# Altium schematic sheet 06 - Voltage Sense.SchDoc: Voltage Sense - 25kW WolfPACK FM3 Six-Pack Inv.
size 431 x 279 mm; Date: 01/2024; DocumentNumber: CRD25DA12N-FMC; Revision: 1.2; SheetNumber: 6; SheetTotal: 8; SheetSize: B
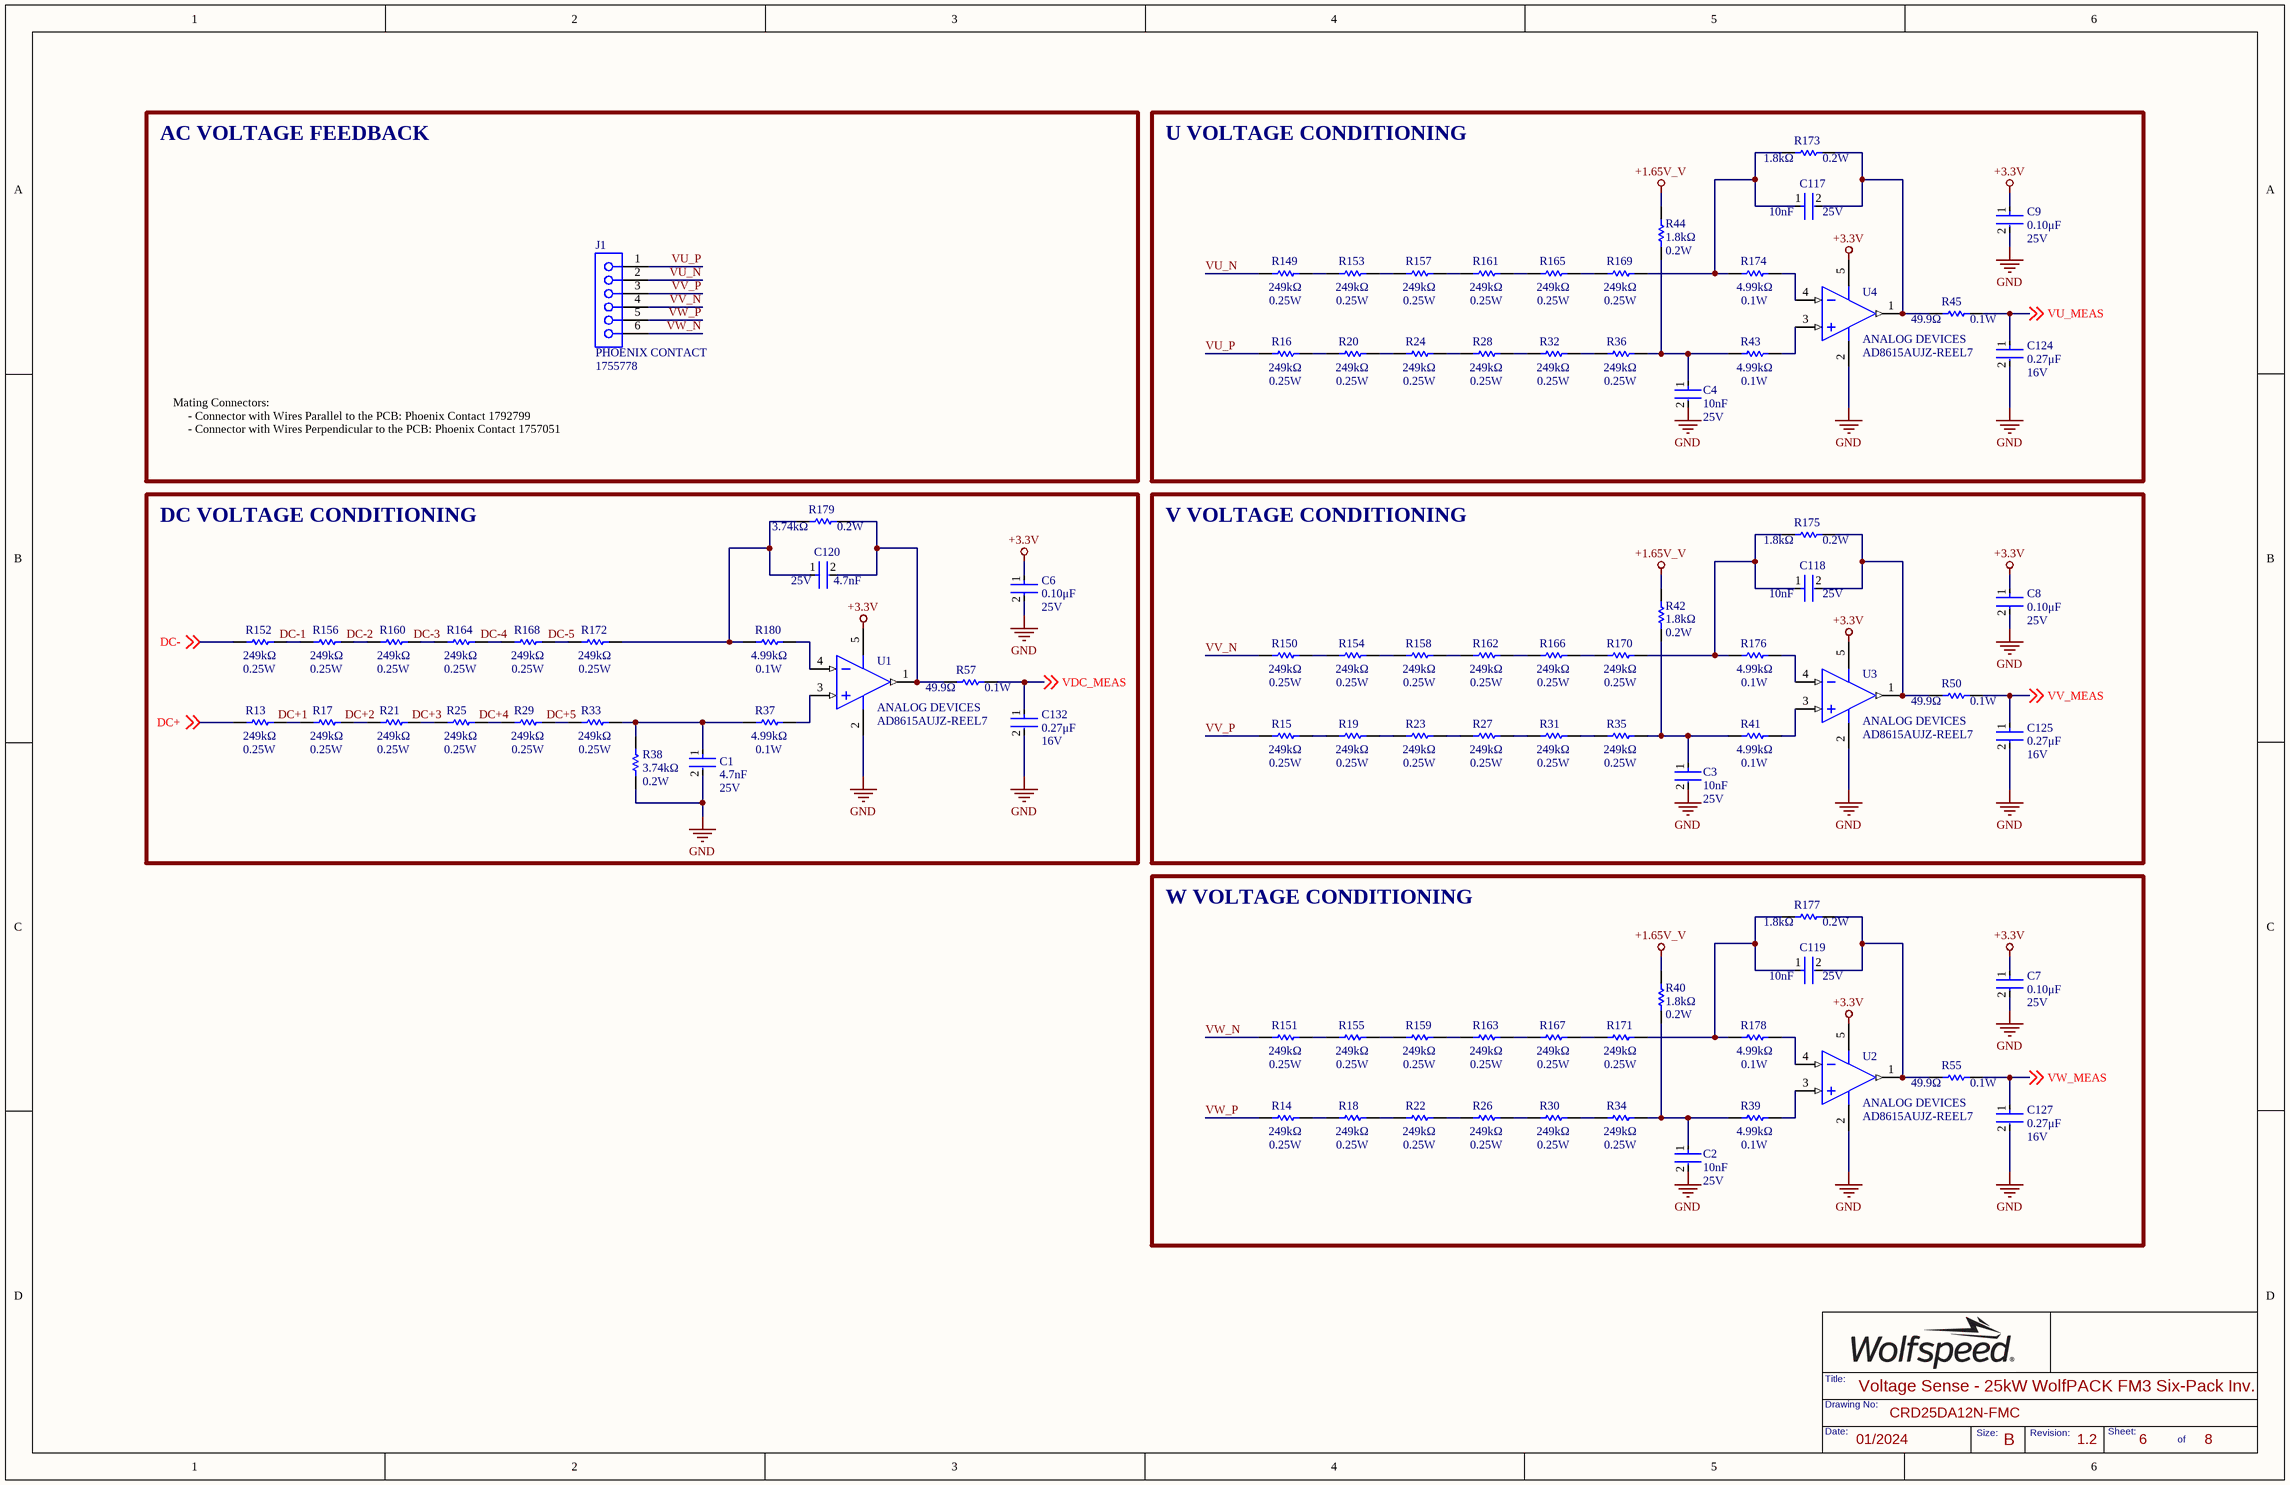
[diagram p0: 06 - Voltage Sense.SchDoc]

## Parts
C1  Voltage Rating: 25V  Capacitance: 4.7nF  [FP-C0603C-CF-IPC_B]  (hidden comment: C0603C472K3RAC7867)
C2  value 10nF  Voltage Rating: 25V  [FP-C0603C-CF-IPC_B]  (hidden comment: CL10B103KA8WPNC)
C3  value 10nF  Voltage Rating: 25V  [FP-C0603C-CF-IPC_B]  (hidden comment: CL10B103KA8WPNC)
C4  value 10nF  Voltage Rating: 25V  [FP-C0603C-CF-IPC_B]  (hidden comment: CL10B103KA8WPNC)
C6  Voltage Rating: 25V  Capacitance: 0.10μF  [FP-C0603C-CF-IPC_B]  (hidden comment: C0603C104K3RACTU)
C7  Voltage Rating: 25V  Capacitance: 0.10μF  [FP-C0603C-CF-IPC_B]  (hidden comment: C0603C104K3RACTU)
C8  Voltage Rating: 25V  Capacitance: 0.10μF  [FP-C0603C-CF-IPC_B]  (hidden comment: C0603C104K3RACTU)
C9  Voltage Rating: 25V  Capacitance: 0.10μF  [FP-C0603C-CF-IPC_B]  (hidden comment: C0603C104K3RACTU)
C117  value 10nF  Voltage Rating: 25V  [FP-C0603C-CF-IPC_B]  (hidden comment: CL10B103KA8WPNC)
C118  value 10nF  Voltage Rating: 25V  [FP-C0603C-CF-IPC_B]  (hidden comment: CL10B103KA8WPNC)
C119  value 10nF  Voltage Rating: 25V  [FP-C0603C-CF-IPC_B]  (hidden comment: CL10B103KA8WPNC)
C120  Voltage Rating: 25V  Capacitance: 4.7nF  [FP-C0603C-CF-IPC_B]  (hidden comment: C0603C472K3RAC7867)
C124  Voltage Rating (DC): 16V  Capacitance: 0.27μF  [FP-GCM188-0_1-IPC_A]  (hidden comment: GCM188R71C274KA37D)
C125  Voltage Rating (DC): 16V  Capacitance: 0.27μF  [FP-GCM188-0_1-IPC_A]  (hidden comment: GCM188R71C274KA37D)
C127  Voltage Rating (DC): 16V  Capacitance: 0.27μF  [FP-GCM188-0_1-IPC_A]  (hidden comment: GCM188R71C274KA37D)
C132  Voltage Rating (DC): 16V  Capacitance: 0.27μF  [FP-GCM188-0_1-IPC_A]  (hidden comment: GCM188R71C274KA37D)
J1  1755778  Manufacturer Print: PHOENIX CONTACT  [1755778]
R13  Resistance: 249kΩ  Power: 0.25W  [RESC3216X65X50NL15T25]  (hidden comment: TNPW1206249KBEEA)
R14  Resistance: 249kΩ  Power: 0.25W  [RESC3216X65X50NL15T25]  (hidden comment: TNPW1206249KBEEA)
R15  Resistance: 249kΩ  Power: 0.25W  [RESC3216X65X50NL15T25]  (hidden comment: TNPW1206249KBEEA)
R16  Resistance: 249kΩ  Power: 0.25W  [RESC3216X65X50NL15T25]  (hidden comment: TNPW1206249KBEEA)
R17  Resistance: 249kΩ  Power: 0.25W  [RESC3216X65X50NL15T25]  (hidden comment: TNPW1206249KBEEA)
R18  Resistance: 249kΩ  Power: 0.25W  [RESC3216X65X50NL15T25]  (hidden comment: TNPW1206249KBEEA)
R19  Resistance: 249kΩ  Power: 0.25W  [RESC3216X65X50NL15T25]  (hidden comment: TNPW1206249KBEEA)
R20  Resistance: 249kΩ  Power: 0.25W  [RESC3216X65X50NL15T25]  (hidden comment: TNPW1206249KBEEA)
R21  Resistance: 249kΩ  Power: 0.25W  [RESC3216X65X50NL15T25]  (hidden comment: TNPW1206249KBEEA)
R22  Resistance: 249kΩ  Power: 0.25W  [RESC3216X65X50NL15T25]  (hidden comment: TNPW1206249KBEEA)
R23  Resistance: 249kΩ  Power: 0.25W  [RESC3216X65X50NL15T25]  (hidden comment: TNPW1206249KBEEA)
R24  Resistance: 249kΩ  Power: 0.25W  [RESC3216X65X50NL15T25]  (hidden comment: TNPW1206249KBEEA)
R25  Resistance: 249kΩ  Power: 0.25W  [RESC3216X65X50NL15T25]  (hidden comment: TNPW1206249KBEEA)
R26  Resistance: 249kΩ  Power: 0.25W  [RESC3216X65X50NL15T25]  (hidden comment: TNPW1206249KBEEA)
R27  Resistance: 249kΩ  Power: 0.25W  [RESC3216X65X50NL15T25]  (hidden comment: TNPW1206249KBEEA)
R28  Resistance: 249kΩ  Power: 0.25W  [RESC3216X65X50NL15T25]  (hidden comment: TNPW1206249KBEEA)
R29  Resistance: 249kΩ  Power: 0.25W  [RESC3216X65X50NL15T25]  (hidden comment: TNPW1206249KBEEA)
R30  Resistance: 249kΩ  Power: 0.25W  [RESC3216X65X50NL15T25]  (hidden comment: TNPW1206249KBEEA)
R31  Resistance: 249kΩ  Power: 0.25W  [RESC3216X65X50NL15T25]  (hidden comment: TNPW1206249KBEEA)
R32  Resistance: 249kΩ  Power: 0.25W  [RESC3216X65X50NL15T25]  (hidden comment: TNPW1206249KBEEA)
R33  Resistance: 249kΩ  Power: 0.25W  [RESC3216X65X50NL15T25]  (hidden comment: TNPW1206249KBEEA)
R34  Resistance: 249kΩ  Power: 0.25W  [RESC3216X65X50NL15T25]  (hidden comment: TNPW1206249KBEEA)
R35  Resistance: 249kΩ  Power: 0.25W  [RESC3216X65X50NL15T25]  (hidden comment: TNPW1206249KBEEA)
R36  Resistance: 249kΩ  Power: 0.25W  [RESC3216X65X50NL15T25]  (hidden comment: TNPW1206249KBEEA)
R37  Power Rating: 0.1W  Resistance: 4.99kΩ  [FP-MCR03-IPC_B]  (hidden comment: RC0603FR-074K99L)
R38  Max Power Dissipation: 0.2W  Resistance: 3.74kΩ  [FP-MCR03-IPC_B]  (hidden comment: ERJ-PB3B3741V)
R39  Power Rating: 0.1W  Resistance: 4.99kΩ  [FP-MCR03-IPC_B]  (hidden comment: RC0603FR-074K99L)
R40  Resistance: 1.8kΩ  Max Power Dissipation: 0.2W  [FP-MCR03-IPC_B]  (hidden comment: ERJ-PB3B1801V)
R41  Power Rating: 0.1W  Resistance: 4.99kΩ  [FP-MCR03-IPC_B]  (hidden comment: RC0603FR-074K99L)
R42  Resistance: 1.8kΩ  Max Power Dissipation: 0.2W  [FP-MCR03-IPC_B]  (hidden comment: ERJ-PB3B1801V)
R43  Power Rating: 0.1W  Resistance: 4.99kΩ  [FP-MCR03-IPC_B]  (hidden comment: RC0603FR-074K99L)
R44  Resistance: 1.8kΩ  Max Power Dissipation: 0.2W  [FP-MCR03-IPC_B]  (hidden comment: ERJ-PB3B1801V)
R45  Resistance: 49.9Ω  Power Rating: 0.1W  [FP-MCR03-IPC_B]  (hidden comment: ERJ-3EKF49R9V)
R50  Resistance: 49.9Ω  Power Rating: 0.1W  [FP-MCR03-IPC_B]  (hidden comment: ERJ-3EKF49R9V)
R55  Resistance: 49.9Ω  Power Rating: 0.1W  [FP-MCR03-IPC_B]  (hidden comment: ERJ-3EKF49R9V)
R57  Resistance: 49.9Ω  Power Rating: 0.1W  [FP-MCR03-IPC_B]  (hidden comment: ERJ-3EKF49R9V)
R149  Resistance: 249kΩ  Power: 0.25W  [RESC3216X65X50NL15T25]  (hidden comment: TNPW1206249KBEEA)
R150  Resistance: 249kΩ  Power: 0.25W  [RESC3216X65X50NL15T25]  (hidden comment: TNPW1206249KBEEA)
R151  Resistance: 249kΩ  Power: 0.25W  [RESC3216X65X50NL15T25]  (hidden comment: TNPW1206249KBEEA)
R152  Resistance: 249kΩ  Power: 0.25W  [RESC3216X65X50NL15T25]  (hidden comment: TNPW1206249KBEEA)
R153  Resistance: 249kΩ  Power: 0.25W  [RESC3216X65X50NL15T25]  (hidden comment: TNPW1206249KBEEA)
R154  Resistance: 249kΩ  Power: 0.25W  [RESC3216X65X50NL15T25]  (hidden comment: TNPW1206249KBEEA)
R155  Resistance: 249kΩ  Power: 0.25W  [RESC3216X65X50NL15T25]  (hidden comment: TNPW1206249KBEEA)
R156  Resistance: 249kΩ  Power: 0.25W  [RESC3216X65X50NL15T25]  (hidden comment: TNPW1206249KBEEA)
R157  Resistance: 249kΩ  Power: 0.25W  [RESC3216X65X50NL15T25]  (hidden comment: TNPW1206249KBEEA)
R158  Resistance: 249kΩ  Power: 0.25W  [RESC3216X65X50NL15T25]  (hidden comment: TNPW1206249KBEEA)
R159  Resistance: 249kΩ  Power: 0.25W  [RESC3216X65X50NL15T25]  (hidden comment: TNPW1206249KBEEA)
R160  Resistance: 249kΩ  Power: 0.25W  [RESC3216X65X50NL15T25]  (hidden comment: TNPW1206249KBEEA)
R161  Resistance: 249kΩ  Power: 0.25W  [RESC3216X65X50NL15T25]  (hidden comment: TNPW1206249KBEEA)
R162  Resistance: 249kΩ  Power: 0.25W  [RESC3216X65X50NL15T25]  (hidden comment: TNPW1206249KBEEA)
R163  Resistance: 249kΩ  Power: 0.25W  [RESC3216X65X50NL15T25]  (hidden comment: TNPW1206249KBEEA)
R164  Resistance: 249kΩ  Power: 0.25W  [RESC3216X65X50NL15T25]  (hidden comment: TNPW1206249KBEEA)
R165  Resistance: 249kΩ  Power: 0.25W  [RESC3216X65X50NL15T25]  (hidden comment: TNPW1206249KBEEA)
R166  Resistance: 249kΩ  Power: 0.25W  [RESC3216X65X50NL15T25]  (hidden comment: TNPW1206249KBEEA)
R167  Resistance: 249kΩ  Power: 0.25W  [RESC3216X65X50NL15T25]  (hidden comment: TNPW1206249KBEEA)
R168  Resistance: 249kΩ  Power: 0.25W  [RESC3216X65X50NL15T25]  (hidden comment: TNPW1206249KBEEA)
R169  Resistance: 249kΩ  Power: 0.25W  [RESC3216X65X50NL15T25]  (hidden comment: TNPW1206249KBEEA)
R170  Resistance: 249kΩ  Power: 0.25W  [RESC3216X65X50NL15T25]  (hidden comment: TNPW1206249KBEEA)
R171  Resistance: 249kΩ  Power: 0.25W  [RESC3216X65X50NL15T25]  (hidden comment: TNPW1206249KBEEA)
R172  Resistance: 249kΩ  Power: 0.25W  [RESC3216X65X50NL15T25]  (hidden comment: TNPW1206249KBEEA)
R173  Resistance: 1.8kΩ  Max Power Dissipation: 0.2W  [FP-MCR03-IPC_B]  (hidden comment: ERJ-PB3B1801V)
R174  Power Rating: 0.1W  Resistance: 4.99kΩ  [FP-MCR03-IPC_B]  (hidden comment: RC0603FR-074K99L)
R175  Resistance: 1.8kΩ  Max Power Dissipation: 0.2W  [FP-MCR03-IPC_B]  (hidden comment: ERJ-PB3B1801V)
R176  Power Rating: 0.1W  Resistance: 4.99kΩ  [FP-MCR03-IPC_B]  (hidden comment: RC0603FR-074K99L)
R177  Resistance: 1.8kΩ  Max Power Dissipation: 0.2W  [FP-MCR03-IPC_B]  (hidden comment: ERJ-PB3B1801V)
R178  Power Rating: 0.1W  Resistance: 4.99kΩ  [FP-MCR03-IPC_B]  (hidden comment: RC0603FR-074K99L)
R179  Max Power Dissipation: 0.2W  Resistance: 3.74kΩ  [FP-MCR03-IPC_B]  (hidden comment: ERJ-PB3B3741V)
R180  Power Rating: 0.1W  Resistance: 4.99kΩ  [FP-MCR03-IPC_B]  (hidden comment: RC0603FR-074K99L)
U1  Manufacturer: ANALOG DEVICES  [ADI-UJ-5_M]  (hidden comment: AD8615AUJZ-REEL7)
U2  Manufacturer: ANALOG DEVICES  [ADI-UJ-5_M]  (hidden comment: AD8615AUJZ-REEL7)
U3  Manufacturer: ANALOG DEVICES  [ADI-UJ-5_M]  (hidden comment: AD8615AUJZ-REEL7)
U4  Manufacturer: ANALOG DEVICES  [ADI-UJ-5_M]  (hidden comment: AD8615AUJZ-REEL7)

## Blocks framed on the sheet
AC VOLTAGE FEEDBACK: J1
U VOLTAGE CONDITIONING: C4 C9 C117 C124 R16 R20 R24 R28 R32 R36 R43-R45 R149 R153 R157 R161 R165 R169 R173 R174 U4
DC VOLTAGE CONDITIONING: C1 C6 C120 C132 R13 R17 R21 R25 R29 R33 R37 R38 R57 R152 R156 R160 R164 R168 R172 R179 R180 U1
V VOLTAGE CONDITIONING: C3 C8 C118 C125 R15 R19 R23 R27 R31 R35 R41 R42 R50 R150 R154 R158 R162 R166 R170 R175 R176 U3
W VOLTAGE CONDITIONING: C2 C7 C119 C127 R14 R18 R22 R26 R30 R34 R39 R40 R55 R151 R155 R159 R163 R167 R171 R177 R178 U2

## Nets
+1.65V_V: R40.2 R42.2 R44.2
+3.3V: C6.1 C7.1 C8.1 C9.1 U1.5(+V) U2.5(+V) U3.5(+V) U4.5(+V)
GND: C1.2 C2.2 C3.2 C4.2 C6.2 C7.2 C8.2 C9.2 C124.2 C125.2 C127.2 C132.2 R38.1 U1.2(-V) U2.2(-V) U3.2(-V) U4.2(-V)
DC+: R13.1 ; off-sheet DC+
DC+1: R13.2 R17.1
DC+2: R17.2 R21.1
DC+3: R21.2 R25.1
DC+4: R25.2 R29.1
DC+5: R29.2 R33.1
DC-: R152.1 ; off-sheet DC-
DC-1: R152.2 R156.1
DC-2: R156.2 R160.1
DC-3: R160.2 R164.1
DC-4: R164.2 R168.1
DC-5: R168.2 R172.1
VDC_MEAS: C132.1 R57.2 ; off-sheet VDC_MEAS
VU_MEAS: C124.1 R45.2 ; off-sheet VU_MEAS
VU_N: J1.2 R149.1
VU_P: J1.1 R16.1
VV_MEAS: C125.1 R50.2 ; off-sheet VV_MEAS
VV_N: J1.4 R150.1
VV_P: J1.3 R15.1
VW_MEAS: C127.1 R55.2 ; off-sheet VW_MEAS
VW_N: J1.6 R151.1
VW_P: J1.5 R14.1
NetC1_1: C1.1 R33.2 R37.1 R38.2
NetC2_1: C2.1 R34.2 R39.1 R40.1
NetC3_1: C3.1 R35.2 R41.1 R42.1
NetC4_1: C4.1 R36.2 R43.1 R44.1
NetC117_1: C117.1 R169.2 R173.2 R174.1
NetC117_2: C117.2 R45.1 R173.1 U4.1(OUT)
NetC118_1: C118.1 R170.2 R175.2 R176.1
NetC118_2: C118.2 R50.1 R175.1 U3.1(OUT)
NetC119_1: C119.1 R171.2 R177.2 R178.1
NetC119_2: C119.2 R55.1 R177.1 U2.1(OUT)
NetC120_1: C120.1 R172.2 R179.1 R180.1
NetC120_2: C120.2 R57.1 R179.2 U1.1(OUT)
NetR14_2: R14.2 R18.1
NetR15_2: R15.2 R19.1
NetR16_2: R16.2 R20.1
NetR18_2: R18.2 R22.1
NetR19_2: R19.2 R23.1
NetR20_2: R20.2 R24.1
NetR22_2: R22.2 R26.1
NetR23_2: R23.2 R27.1
NetR24_2: R24.2 R28.1
NetR26_2: R26.2 R30.1
NetR27_2: R27.2 R31.1
NetR28_2: R28.2 R32.1
NetR30_2: R30.2 R34.1
NetR31_2: R31.2 R35.1
NetR32_2: R32.2 R36.1
NetR37_2: R37.2 U1.3(+IN)
NetR39_2: R39.2 U2.3(+IN)
NetR41_2: R41.2 U3.3(+IN)
NetR43_2: R43.2 U4.3(+IN)
NetR149_2: R149.2 R153.1
NetR150_2: R150.2 R154.1
NetR151_2: R151.2 R155.1
NetR153_2: R153.2 R157.1
NetR154_2: R154.2 R158.1
NetR155_2: R155.2 R159.1
NetR157_2: R157.2 R161.1
NetR158_2: R158.2 R162.1
NetR159_2: R159.2 R163.1
NetR161_2: R161.2 R165.1
NetR162_2: R162.2 R166.1
NetR163_2: R163.2 R167.1
NetR165_2: R165.2 R169.1
NetR166_2: R166.2 R170.1
NetR167_2: R167.2 R171.1
NetR174_2: R174.2 U4.4(-IN)
NetR176_2: R176.2 U3.4(-IN)
NetR178_2: R178.2 U2.4(-IN)
NetR180_2: R180.2 U1.4(-IN)

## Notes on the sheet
- Mating Connectors:
  - Connector with Wires Parallel to the PCB: Phoenix Contact 1792799
  - Connector with Wires Perpendicular to the PCB: Phoenix Contact 1757051

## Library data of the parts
C1 C120 = C0603C472K3RAC7867: CAP CER 4700PF 25V 10% X7R 0603; Manufacturer: KEMET; Manufacturer Part Number: C0603C472K3RACTU; Dielectric Material: Ceramic; Value: 4.7nF
C2-C4 C117-C119 = CL10B103KA8WPNC: CAP CER 10000PF 25V X7R 0603; Manufacturer: SAMSUNG; Tolerance: 10%
C6-C9 = CMP-2006-03057-2: CAP CER 0.1UF 25V X7R 0603; Manufacturer: KEMET; Value: 0.10μF; Material: Ceramic; Tolerance: 0.1; Temperature Coefficient: 30ppm/°C; Automotive Grade: Grade 1
C124 C125 C127 C132 = CMP-06035-043171-1: CAP CER 0.27UF 16V X7R 0603; Manufacturer: MURATA; Tolerance: 10%; Value: 0.27μF
J1 = 1755778: TERM BLOCK HDR 6POS VERT 5.08MM; Voltage Rating: 250V; Current Rating: 12A; Number of Positions: 6; Number of Levels: 1; Voltage: 300V; Gender: Male; Connector Type: Plug; Approvals: UL,CSA,VDE,cULus,CB,EAC
R13-R36 R149-R172 = CMP-2003-04604-1: RES 249K OHM 0.1% 1/4W 1206; Manufacturer: VISHAY DALE; Value: 249kΩ
R37 R39 R41 R43 R174 R176 R178 R180 = RC0603FR-074K99L: RES 4.99K OHM 1% 1/10W 0603; Manufacturer: YAGEO; Voltage Rating: 75V; Temperature Coefficient: 100ppm/°C; Voltage Rating (DC): 50V; Value: 4.99kΩ
R38 R179 = ERJ-PB3B3741V: RES SMD 3.74K OHM 0.1% 1/5W 0603; Manufacturer: PANASONIC; Temperature Coefficient: 50ppm/°C; Value: 3.74kΩ
R40 R42 R44 R173 R175 R177 = ERJ-PB3B1801V: RES SMD 1.8K OHM 0.1% 1/5W 0603; Manufacturer: PANASONIC; Temperature Coefficient: 50ppm/°C; Value: 1.8kΩ
R45 R50 R55 R57 = ERJ-3EKF49R9V: RES SMD 49.9 OHM 1% 1/10W 0603; Manufacturer: PANASONIC; Temperature Coefficient: 100ppm/°C; Voltage Rating: 75V; Max Power Dissipation: 100mW; Voltage Rating (DC): 50V; Working Voltage: 6V; Value: 49.9Ω
U1-U4 = CMP-0384-02059-2: IC OPAMP GP 1 CIRCUIT TSOT23-5; Generic Part Number: AD8615; Iq/Amp: 1.7mA; V Span Max: 6V; Amplifiers Per Package: 1; Small Signal Bandwidth: 23MHz; Input Offset Voltage: 80uV; V Span Min: 2.7V; Slew Rate: 12V/us; Input Bias Current: 200fA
